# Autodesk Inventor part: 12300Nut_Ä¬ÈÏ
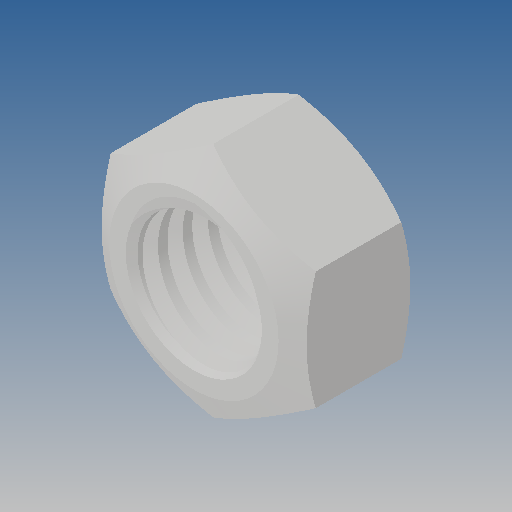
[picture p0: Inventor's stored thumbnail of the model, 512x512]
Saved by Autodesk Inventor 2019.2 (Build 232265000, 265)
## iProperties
Created: 2010-06
Part Number: 12300Nut_Ä¬ÈÏ
Material: Ogólny
Document SubType Name: Modeling
Designer: CADENGINEERING4
Density: 1 g/cm^3
Appearance: Domyślna
Author: CADENGINEERING4
Revision Number: ÈÎºÎ
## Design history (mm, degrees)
feature "NONE"
node "Bryła1"
